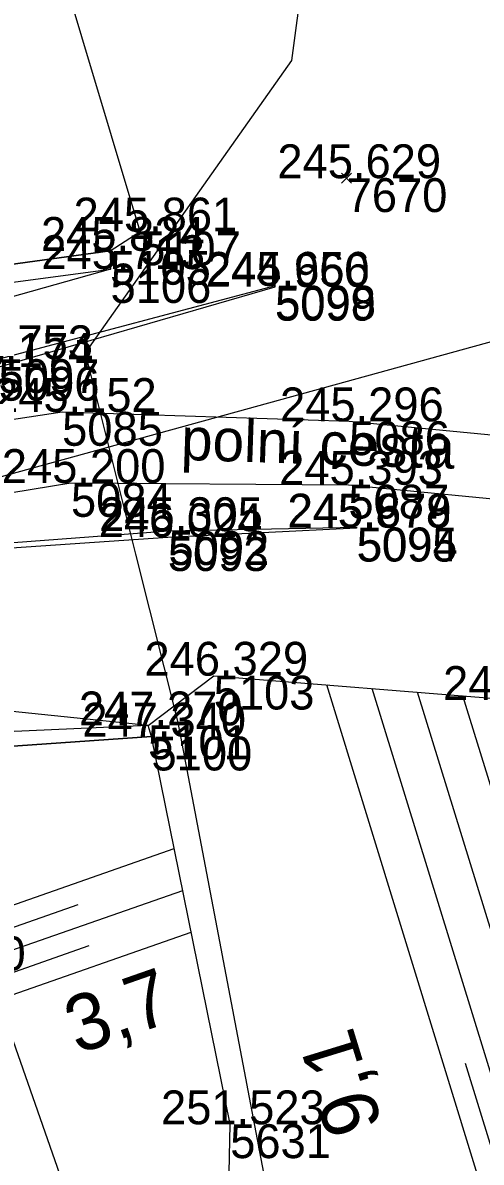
# Model space of a CAD drawing. Extents: x -809970 to -809480, y -1011362 to -1010672.
# Drawn here: x -809829.08 to -809812.83, y -1011010.25 to -1010969.85 of the extents above; entities that cross this region are included whole.
import ezdxf

# ---------------------------------------------------------------- set-up
doc = ezdxf.new("R2010")
doc.units = 0
for name, color, linetype in [('Vrstva 13', 7, 'Continuous'), ('Vrstva 18', 7, 'Continuous'), ('Vrstva 4', 7, 'Continuous'), ('Vrstva 48', 7, 'Continuous'), ('Vrstva 49', 7, 'Continuous'), ('Vrstva 51', 7, 'Continuous'), ('Vrstva 53', 7, 'Continuous'), ('Vrstva 60', 7, 'Continuous'), ('Vrstva 61', 7, 'Continuous')]:
    doc.layers.add(name, color=color, linetype=linetype)

msp = doc.modelspace()

# ---------------------------------------------------------------- linework, layer by layer
at = {"layer": 'Vrstva 13'}
for points in [[(-809820.14, -1010979.21), (-809820.132, -1010979.173), (-809829.939, -1010981.776), (-809837.836, -1010983.041), (-809842.641, -1010984.432), (-809846.327, -1010986.353), (-809846.733, -1010986.717), (-809842.555, -1010984.599), (-809837.625, -1010983.192), (-809829.93, -1010982.048), (-809820.14, -1010979.21)], [(-809817.231, -1010987.744), (-809823.915, -1010987.873), (-809836.01, -1010988.78), (-809841.685, -1010990.477), (-809848.428, -1010993.714), (-809851.384, -1010995.767), (-809851.225, -1010995.731), (-809848.524, -1010993.918), (-809841.495, -1010990.513), (-809836.067, -1010988.917), (-809823.939, -1010988.086), (-809817.248, -1010987.751), (-809817.231, -1010987.744)]]:
    msp.add_lwpolyline(points, dxfattribs=at)
at = {"layer": 'Vrstva 18'}
msp.add_line((-809776.853, -1010971.329), (-809835.71, -1010987.562), dxfattribs=at)
for points in [[(-809825.985, -1010977.935), (-809837.013, -1010979.451), (-809837.883, -1010979.54), (-809838.423, -1010979.516)], [(-809825.985, -1010977.935), (-809825.969, -1010978.581), (-809837.905, -1010981.945), (-809837.764, -1010982.524)], [(-809838.271, -1010980.078), (-809837.765, -1010980.109), (-809837.39, -1010980.112), (-809825.969, -1010978.581)], [(-809824.518, -1010995.159), (-809824.64, -1010994.76), (-809834.382, -1010993.76), (-809834.561, -1010993.15)], [(-809824.64, -1010994.76), (-809833.083, -1010995.146), (-809833.623, -1010995.188), (-809834.189, -1010995.204)], [(-809834.017, -1010995.842), (-809832.993, -1010995.743), (-809824.518, -1010995.159)]]:
    msp.add_lwpolyline(points, dxfattribs=at)
at = {"layer": 'Vrstva 4'}
msp.add_lwpolyline([(-809817.164, -1011036.691), (-809823.084, -1011022.979), (-809826.372, -1011014.673), (-809832.993, -1010995.743), (-809834.017, -1010995.842), (-809834.085, -1010995.877), (-809834.105, -1010995.845)], dxfattribs=at)
at = {"layer": 'Vrstva 48'}
for p, q in [((-809809.99, -1011020.331), (-809818.307, -1010993.324)), ((-809808.556, -1011019.89), (-809816.697, -1010993.454)), ((-809807.123, -1011019.448), (-809815.087, -1010993.585)), ((-809805.689, -1011019.007), (-809813.478, -1010993.716)), ((-809830.926, -1011001.653), (-809823.712, -1010999.13)), ((-809830.431, -1011003.069), (-809823.411, -1011000.614)), ((-809830.678, -1011002.361), (-809827.12, -1011001.117)), ((-809829.935, -1011004.485), (-809823.11, -1011002.098)), ((-809830.183, -1011003.777), (-809826.722, -1011002.567)), ((-809809.273, -1011020.11), (-809813.388, -1011006.75))]:
    msp.add_line(p, q, dxfattribs=at)
at = {"layer": 'Vrstva 49'}
for p, q in [((-809817.778, -1010975.181), (-809817.424, -1010975.535)), ((-809817.778, -1010975.535), (-809817.424, -1010975.181))]:
    msp.add_line(p, q, dxfattribs=at)
for points in [[(-809856.883, -1010875.823), (-809855.422, -1010883.15), (-809852.222, -1010901.25), (-809848.214, -1010923.392), (-809845.696, -1010934.941), (-809844.027, -1010949.48), (-809841.894, -1010960.179), (-809838.847, -1010973.75), (-809838.297, -1010976.333), (-809838.163, -1010976.258), (-809836.936, -1010979.029), (-809837.013, -1010979.451), (-809825.985, -1010977.935), (-809824.923, -1010977.248)], [(-809824.923, -1010977.248), (-809832.146, -1010953.133), (-809837.944, -1010921.765), (-809839.29, -1010906.656), (-809832.688, -1010885.218), (-809835.079, -1010880.738), (-809839.978, -1010876.967), (-809844.518, -1010876.01), (-809844.618, -1010877), (-809856.883, -1010875.823)], [(-809824.518, -1010995.159), (-809824.64, -1010994.76), (-809822.313, -1010992.998), (-809811.732, -1010993.858)], [(-809823.22, -1011017.736), (-809821.817, -1011012.906), (-809821.728, -1011008.905), (-809824.518, -1010995.159), (-809832.993, -1010995.743)], [(-809820.959, -1011021.87), (-809823.22, -1011017.736), (-809826.372, -1011014.673), (-809832.993, -1010995.743)]]:
    msp.add_lwpolyline(points, dxfattribs=at)
at = {"layer": 'Vrstva 51'}
for points in [[(-809868.177, -1010980.133), (-809861.522, -1010984.435), (-809856.273, -1010987.12), (-809851.693, -1010988.364), (-809846.095, -1010987.906), (-809837.047, -1010985.065), (-809827.686, -1010983.646), (-809817.51, -1010983.979), (-809809.643, -1010984.731), (-809805.029, -1010984.43)], [(-809869.144, -1010983.263), (-809862.744, -1010986.475), (-809856.658, -1010989.933), (-809852.549, -1010991.524), (-809844.992, -1010990.276), (-809835.966, -1010987.57), (-809827.372, -1010986.165), (-809817.539, -1010986.227), (-809810.453, -1010986.917), (-809804.657, -1010986.868)]]:
    msp.add_lwpolyline(points, dxfattribs=at)
at = {"layer": 'Vrstva 53'}
msp.add_lwpolyline([(-809848.47, -1010824.63), (-809848.99, -1010834.52), (-809828.94, -1010831.94), (-809811.76, -1010846.11), (-809806.99, -1010849.89), (-809798.33, -1010856.76), (-809803.49, -1010861.61), (-809820.27, -1010877.38), (-809819.54, -1010907.65), (-809817.34, -1010954.54), (-809819.55, -1010971.19), (-809826.87, -1010981.55), (-809825.08, -1010988.69), (-809823.59, -1010994.66), (-809817.83, -1011024.91), (-809805.06, -1011048.21)], dxfattribs=at)
at = {"layer": 'Vrstva 60'}
for p, q in [((-809817.601, -1010975.358), (-809817.601, -1010975.358)), ((-809824.923, -1010977.248), (-809824.923, -1010977.248)), ((-809825.985, -1010977.935), (-809825.985, -1010977.935)), ((-809825.969, -1010978.581), (-809825.969, -1010978.581)), ((-809820.14, -1010979.21), (-809820.14, -1010979.21)), ((-809820.132, -1010979.173), (-809820.132, -1010979.173)), ((-809827.686, -1010983.646), (-809827.686, -1010983.646)), ((-809817.51, -1010983.979), (-809817.51, -1010983.979)), ((-809827.372, -1010986.165), (-809827.372, -1010986.165)), ((-809817.539, -1010986.227), (-809817.539, -1010986.227)), ((-809823.915, -1010987.873), (-809823.915, -1010987.873)), ((-809817.248, -1010987.751), (-809817.248, -1010987.751)), ((-809817.231, -1010987.744), (-809817.231, -1010987.744)), ((-809823.939, -1010988.086), (-809823.939, -1010988.086)), ((-809822.313, -1010992.998), (-809822.313, -1010992.998)), ((-809824.64, -1010994.76), (-809824.64, -1010994.76)), ((-809824.518, -1010995.159), (-809824.518, -1010995.159)), ((-809821.728, -1011008.905), (-809821.728, -1011008.905))]:
    msp.add_line(p, q, dxfattribs=at)

# ---------------------------------------------------------------- texts
at = {"layer": 'Vrstva 48'}
for s, rotation, p in [('3,7', 19.2779, (-809827.139, -1011006.432)), ('9,1', 107.1167, (-809816.319, -1011008.936))]:
    msp.add_text(s, height=2, rotation=rotation, dxfattribs=at).set_placement(p)
at = {"layer": 'Vrstva 51'}
msp.add_text('polní cesta', height=1.5, rotation=358.1257, dxfattribs=at).set_placement((-809823.487, -1010985.343))
at = {"layer": 'Vrstva 60'}
for s, p in [('7670', (-809817.601, -1010976.558)), ('5107', (-809824.923, -1010978.448)), ('5105', (-809825.985, -1010979.135)), ('5106', (-809825.969, -1010979.781)), ('5099', (-809820.14, -1010980.41)), ('5098', (-809820.132, -1010980.373)), ('5097', (-809829.939, -1010982.976)), ('5096', (-809829.93, -1010983.248)), ('5085', (-809827.686, -1010984.846)), ('5086', (-809817.51, -1010985.179)), ('5084', (-809827.372, -1010987.365)), ('5087', (-809817.539, -1010987.427)), ('5092', (-809823.915, -1010989.073)), ('5095', (-809817.248, -1010988.951)), ('5094', (-809817.231, -1010988.944)), ('5093', (-809823.939, -1010989.286)), ('5103', (-809822.313, -1010994.198)), ('5101', (-809824.64, -1010995.96)), ('5100', (-809824.518, -1010996.359)), ('4940', (-809832.548, -1011003.445)), ('5631', (-809821.728, -1011010.105))]:
    msp.add_text(s, height=1.2, dxfattribs=at).set_placement(p)
at = {"layer": 'Vrstva 61'}
for s, p in [('245.629', (-809820.055, -1010975.358)), ('245.861', (-809827.28, -1010977.248)), ('245.824', (-809828.436, -1010977.935)), ('245.713', (-809828.421, -1010978.581)), ('244.960', (-809822.591, -1010979.21)), ('245.656', (-809822.584, -1010979.173)), ('245.753', (-809832.391, -1010981.776)), ('245.174', (-809832.381, -1010982.048)), ('245.152', (-809830.134, -1010983.646)), ('245.296', (-809819.962, -1010983.979)), ('245.200', (-809829.823, -1010986.165)), ('245.393', (-809819.991, -1010986.227)), ('245.305', (-809826.371, -1010987.873)), ('245.878', (-809819.702, -1010987.751)), ('245.679', (-809819.685, -1010987.744)), ('246.024', (-809826.39, -1010988.086)), ('246.329', (-809824.767, -1010992.998)), ('246.464', (-809814.183, -1010993.858)), ('247.270', (-809827.091, -1010994.76)), ('247.340', (-809826.969, -1010995.159)), ('251.523', (-809824.18, -1011008.905))]:
    msp.add_text(s, height=1.2, dxfattribs=at).set_placement(p)

doc.saveas('drawing.dxf')
